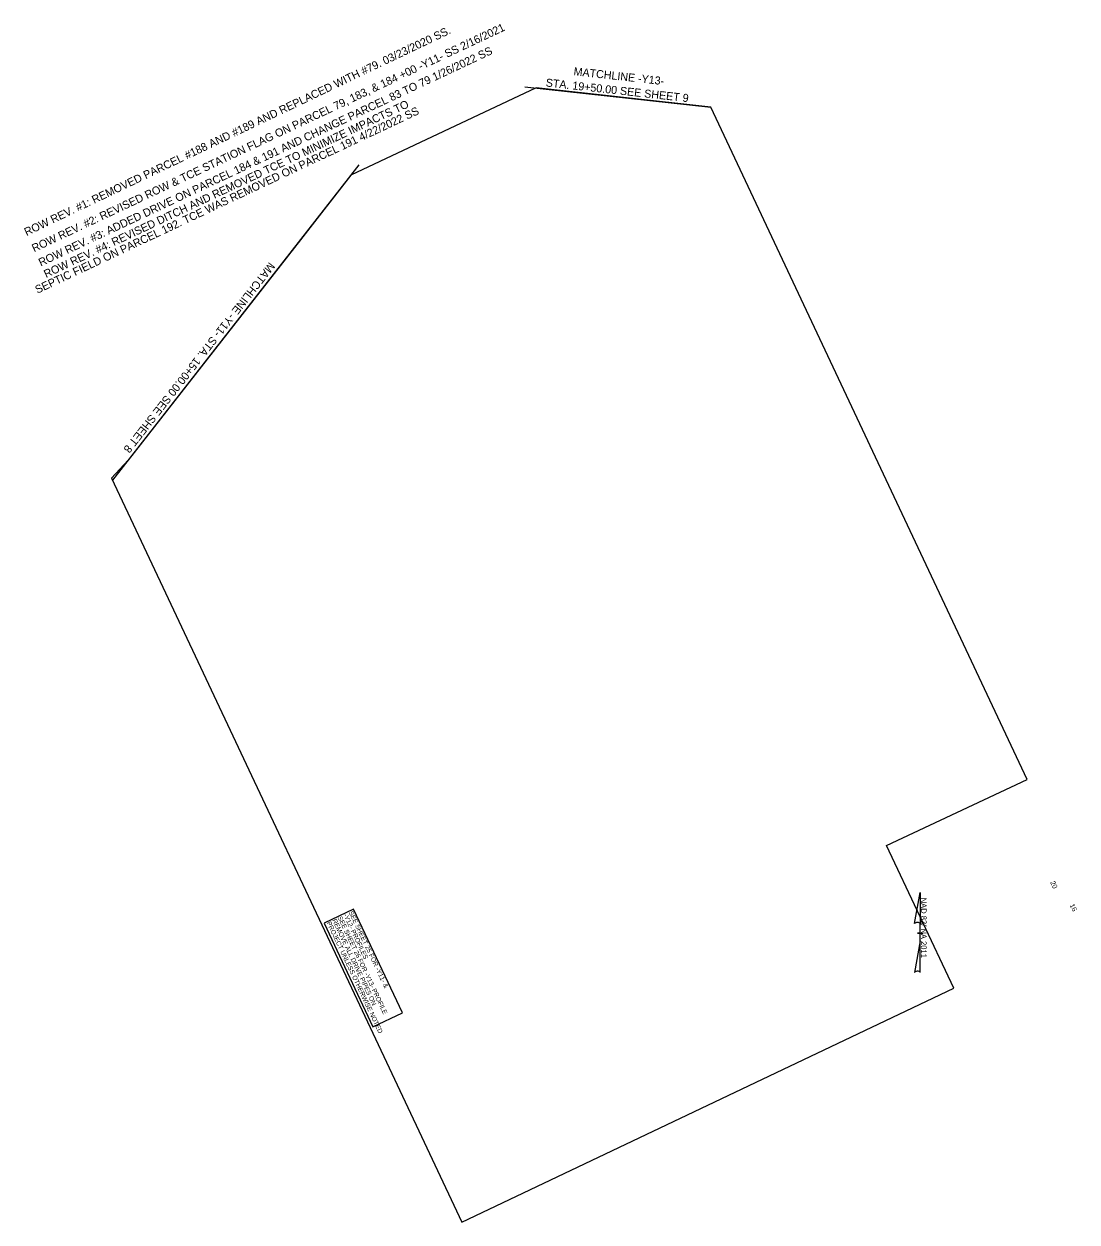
# Model space of a CAD drawing. Extents: x 2326673 to 2328252, y 600427 to 602223.
import ezdxf

# ---------------------------------------------------------------- set-up
doc = ezdxf.new("R2010")
doc.units = 0
for name, color, linetype in [('Matchline', 7, 'Continuous'), ('Prop North Arrow NAD83 for Plan Sheets CELL', 7, 'Continuous'), ('Prop PHM Black Element Wt 5', 7, 'Continuous'), ('Prop PHM Label CELL', 7, 'Continuous'), ('Scratch_Level_4', 7, 'Continuous'), ('Sheet Data Field CELL', 7, 'Continuous'), ('Sheet Layout Plan Border', 7, 'Continuous')]:
    doc.layers.add(name, color=color, linetype=linetype)

msp = doc.modelspace()

# ---------------------------------------------------------------- linework, layer by layer
at = {"layer": 'Matchline'}
for p, q in [((2327424, 602129.3), (2327703.3, 602098.4)), ((2327175.3, 602012.2), (2326805.9, 601539.5))]:
    msp.add_line(p, q, dxfattribs=at)
at = {"layer": 'Prop North Arrow NAD83 for Plan Sheets CELL'}
for p, q in [((2328008.9, 600874.6), (2328017.1, 600921)), ((2328017.1, 600921), (2328017.1, 600921)), ((2328017.1, 600921), (2328017.1, 600921)), ((2328017.1, 600921), (2328017.1, 600873.2)), ((2328017.1, 600848.4), (2328017.1, 600874.6)), ((2328017.1, 600873.2), (2328017.1, 600874.5)), ((2328017.1, 600848.4), (2328008.8, 600801.1)), ((2328016.7, 600860), (2328013.1, 600860)), ((2328013.1, 600860), (2328013.1, 600860)), ((2328013.2, 600860), (2328021.2, 600860)), ((2328017.2, 600801.3), (2328017.1, 600848.4))]:
    msp.add_line(p, q, dxfattribs=at)
for centre, start_param, end_param in [((2328013, 600874.1), 0.216388, 2.908219), ((2328013, 600801), 0.201328, 3.141593)]:
    msp.add_ellipse(centre, major_axis=(4.23, -0.03), ratio=0.461098, start_param=start_param, end_param=end_param, dxfattribs=at)
at = {"layer": 'Prop PHM Black Element Wt 5'}
msp.add_lwpolyline([(2327196.2, 600719.6), (2327240.5, 600740.5), (2327167.3, 600895.9), (2327123, 600875)], close=True, dxfattribs=at)
at = {"layer": 'Sheet Layout Plan Border'}
msp.add_lwpolyline([(2327163, 601996.4), (2327087.5, 601899.8), (2326829.3, 601569.5), (2326804.5, 601542.4), (2327329.8, 600426.9), (2328067.5, 600777.8), (2327966.8, 600991.3), (2328177.8, 601090.7), (2327703.3, 602098.4), (2327441.1, 602127.4)], close=True, dxfattribs=at)

# ---------------------------------------------------------------- texts
at = {"layer": 'Matchline'}
for s, rotation, p in [('MATCHLINE -Y13-', 353.6883, (2327496.9, 602146.6)), ('STA. 19+50.00 SEE SHEET 9', 353.6883, (2327455.1, 602129.7)), ('MATCHLINE -Y11- STA. 15+00.00 SEE SHEET 8', 231.9871, (2327041, 601866.9))]:
    msp.add_text(s, height=12, rotation=rotation, dxfattribs=at).set_placement(p)
at = {"layer": 'Prop North Arrow NAD83 for Plan Sheets CELL'}
msp.add_text('NAD 83/ NA 2011', height=8.5, rotation=270, dxfattribs=at).set_placement((2328018.3, 600913.3))
at = {"layer": 'Prop PHM Label CELL'}
for s, p in [('REMOVE ALL DRIVE PIPES ON ', (2327135.1, 600879.5)), ('SEE SHEET 26 FOR -Y13- PROFILE', (2327143.4, 600883.4)), ('-Y12- PROFILES', (2327151.7, 600887.3)), ('SEE SHEET 25 FOR -Y11- &', (2327160, 600891.2)), ('PROJECT UNLESS OTHERWISE NOTED', (2327126.8, 600875.6))]:
    msp.add_text(s, height=7, rotation=295.2156, dxfattribs=at).set_placement(p)
at = {"layer": 'Scratch_Level_4'}
for s, rotation, p in [('ROW REV. #1: REMOVED PARCEL #188 AND #189 AND REPLACED WITH #79. 03/23/2020 SS.', 25.5302, (2326676.9, 601905.2)), ('ROW REV. #2: REVISED ROW & TCE STATION FLAG ON PARCEL 79, 183, & 184 +00 -Y11- SS 2/16/2021', 25.2155, (2326688.2, 601880.9)), ('ROW REV. #3: ADDED DRIVE ON PARCEL 184 & 191 AND CHANGE PARCEL 83 TO 79 1/26/2022 SS', 25.2155, (2326698.3, 601859.5)), ('ROW REV. #4: REVISED DITCH AND REMOVED TCE TO MINIMIZE IMPACTS TO ', 25.2155, (2326706.2, 601842.2)), ('          SEPTIC FIELD ON PARCEL 192. TCE WAS REMOVED ON PARCEL 191 4/22/2022 SS', 25.2155, (2326652.8, 601799.7))]:
    msp.add_text(s, height=12, rotation=rotation, dxfattribs=at).set_placement(p)
at = {"layer": 'Sheet Data Field CELL'}
for s, p in [('20', (2328212, 600936.3)), ('16', (2328241.2, 600902.1))]:
    msp.add_text(s, height=7.5, rotation=295.2156, dxfattribs=at).set_placement(p)

doc.saveas('drawing.dxf')
